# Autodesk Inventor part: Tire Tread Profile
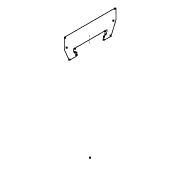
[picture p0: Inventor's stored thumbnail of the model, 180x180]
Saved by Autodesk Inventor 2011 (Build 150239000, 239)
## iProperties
Created: 2010-04
Part Number: Tire Tread Profile
Document SubType Name: Modeling
Designer: Phil
Density: 1 g/cm^3
Author: Phil
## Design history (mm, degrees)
sketch "Sketch1"
  geometry: L1 (50.5, -11.15)-(46.304, -11.15); L2 (41.191, 9.064)-(45.913, 11.07); L3 (43.903, 7.281)-(42.907, 6.958); L4 (42.7, 6.673)-(42.7, 6.074); L5 (42.462, 5.78)-(41.462, 5.568); L6 (41.1, 5.861)-(41.1, 8.926); L7 (45.913, -11.07)-(41.191, -9.064); L8 (42.907, -6.958)-(43.903, -7.281); L9 (42.7, -6.074)-(42.7, -6.673); L10 (41.1, -8.926)-(41.1, -5.861); L11 (41.462, -5.568)-(42.462, -5.78); L12 (46.304, 11.15)-(50.5, 11.15); L13 (44.45, -7.262)-(44.45, 7.262); L14 (50.8, 10.85)-(50.8, -10.85); A1 r 1 centre (46.304, -10.15) between (45.913, -11.07) and (46.304, -11.15); A2 r 0.3 centre (50.5, -10.85) between (50.5, -11.15) and (50.8, -10.85); A3 r 0.8 centre (44.15, -6.521) between (43.903, -7.281) and (44.45, -7.262); A4 r 0.8 centre (44.15, 6.521) between (44.45, 7.262) and (43.903, 7.281); A5 r 0.3 centre (43, 6.673) between (42.907, 6.958) and (42.7, 6.673); A6 r 0.15 centre (41.25, 8.926) between (41.191, 9.064) and (41.1, 8.926); A7 r 0.3 centre (42.4, 6.074) between (42.462, 5.78) and (42.7, 6.074); A8 r 0.3 centre (41.4, 5.861) between (41.1, 5.861) and (41.462, 5.568); A9 r 0.3 centre (43, -6.673) between (42.7, -6.673) and (42.907, -6.958); A10 r 0.15 centre (41.25, -8.926) between (41.1, -8.926) and (41.191, -9.064); A11 r 0.3 centre (42.4, -6.074) between (42.7, -6.074) and (42.462, -5.78); A12 r 0.3 centre (41.4, -5.861) between (41.462, -5.568) and (41.1, -5.861); A13 r 1 centre (46.304, 10.15) between (46.304, 11.15) and (45.913, 11.07); A14 r 0.3 centre (50.5, 10.85) between (50.8, 10.85) and (50.5, 11.15); 2 further points
  constraints: 28 end point, 28 point on circle, 14 centre point, 2 tangent, 1 midpoint, 1 parallel
